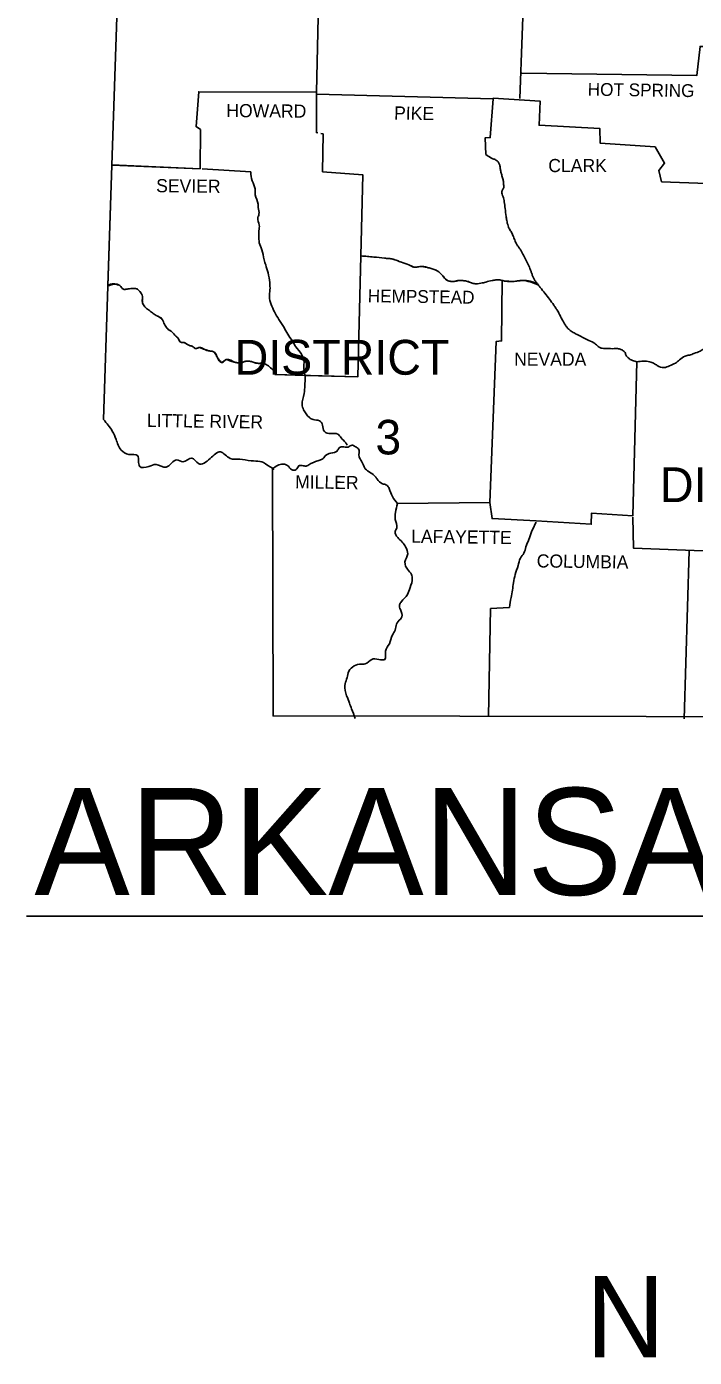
# Model space of a CAD drawing. Extents: x -17742 to 32032, y -17264 to 5867.
# Drawn here: x -17742 to -16539, y 1744 to 4141 of the extents above; entities that cross this region are included whole.
import ezdxf

# ---------------------------------------------------------------- set-up
doc = ezdxf.new("R2010")
doc.units = 0
for name, color, linetype in [('1', 7, 'Continuous'), ('2', 7, 'Continuous'), ('3', 7, 'Continuous'), ('R_Annotation', 7, 'Continuous')]:
    doc.layers.add(name, color=color, linetype=linetype)

msp = doc.modelspace()

# ---------------------------------------------------------------- linework, layer by layer
at = {"layer": '1'}
msp.add_line((-17741.9, 2539.3), (-14228.8, 2539.3), dxfattribs=at)
for points in [[(-16759.7, 4833.7), (-16761.9, 4754.5), (-16887.4, 4753.9), (-16903.9, 4739.6), (-16913.3, 4717.6), (-16927, 4718.7), (-16927.6, 4706), (-16943.5, 4704.4), (-16943, 4692.8), (-17022.8, 4695), (-17025.5, 4686.2), (-17058.6, 4685.1), (-17059.7, 4363.2), (-17087.2, 4362.6), (-17085, 4346.1), (-17111.4, 4346.7), (-17111.9, 4334.6), (-17137.8, 4334.6), (-17137.3, 4325.8), (-17175.8, 4324.7), (-17176.3, 4291.1), (-17213.8, 4294.4), (-17219.8, 4023.6)], [(-17563.4, 4638.6), (-17588.2, 3891.9)], [(-16840.6, 4354.9), (-16853.3, 4012.1)], [(-16849.4, 4057.7), (-16534.6, 4053.3), (-16528.6, 4105.6), (-16503.8, 4105.6), (-16503.3, 4149.6), (-16384.4, 4148), (-16385.5, 4121.6), (-16354.7, 4119.4), (-16354.7, 4070.9), (-16334.8, 4069.3)], [(-17219.8, 4019.8), (-17219.8, 3950.4), (-17217.5, 3950)], [(-16901.3, 4011.4), (-16901.2, 4012.6), (-16816.4, 4007.1), (-16818.6, 3963.6), (-16709.1, 3957.6), (-16708.5, 3931.2), (-16609.5, 3925.1), (-16592.4, 3895.4), (-16602.9, 3882.2), (-16597.9, 3861.8), (-16239.1, 3848.6)], [(-17212.1, 3949), (-17207.7, 3948.2), (-17208.8, 3880), (-17136.2, 3874.5), (-17139.7, 3728.4)], [(-17425.7, 3885.2), (-17338.1, 3880)], [(-17595.4, 3674.1), (-17603.4, 3433.6)], [(-16885.2, 3684.6), (-16886.3, 3575.1), (-16896.2, 3574), (-16907.2, 3283.9)], [(-16642.5, 3537.6), (-16649.6, 3260.3), (-16723.9, 3265.2), (-16724.5, 3244.9), (-16823.6, 3250.9)], [(-17299.1, 3345), (-17298, 2899.8), (-15280.9, 2896.5)], [(-16823.6, 3250.9), (-16903.4, 3255.3), (-16907.2, 3283.9), (-17074, 3282.3)], [(-16413.5, 3193.1), (-16648.5, 3201.9), (-16649.6, 3257.5)], [(-16548.4, 3197), (-16557.2, 2894.8)], [(-16872, 3095.2), (-16906.1, 3093), (-16910, 2899.2)]]:
    msp.add_lwpolyline(points, dxfattribs=at)
for points in [[(-17338.1, 3880), (-17335.4, 3863.5), (-17330.4, 3849.1), (-17329.9, 3838.1), (-17324.9, 3821.6), (-17324.9, 3815.6), (-17323.3, 3803.5), (-17325.5, 3796.9), (-17322.7, 3783.7), (-17323.3, 3773.8), (-17323.3, 3765.5), (-17322.7, 3751.7), (-17318.3, 3739.6), (-17313.9, 3721.5), (-17311.2, 3712.1), (-17306.8, 3697.8), (-17304, 3680.2), (-17303.5, 3667), (-17304.6, 3654.9), (-17301.3, 3641.1), (-17295.2, 3627.4), (-17287.5, 3614.1), (-17278.2, 3599.3), (-17271.5, 3587.7), (-17263.3, 3575.1), (-17256.7, 3564.6), (-17246.8, 3551.4), (-17242.4, 3540.4), (-17242.4, 3525), (-17240.2, 3510.7), (-17240.7, 3494.7), (-17241.8, 3480.4), (-17245.7, 3460.6), (-17242.9, 3451.2), (-17232.5, 3437.5), (-17225.9, 3433.6), (-17214.3, 3431.4), (-17208.8, 3423.7), (-17205.5, 3412.2), (-17193.9, 3408.3), (-17181.3, 3407.2), (-17175.2, 3400.6), (-17167, 3391.8), (-17164.2, 3387.4)], [(-16819.8, 3675.6), (-16816.4, 3671.4), (-16799.9, 3650.5), (-16792.2, 3639.9), (-16788.6, 3634.5), (-16785, 3629), (-16782.8, 3625.1), (-16780.8, 3621.1), (-16778.9, 3617), (-16776.8, 3613), (-16771.2, 3603.7), (-16768, 3599.3), (-16766.2, 3597.3), (-16764.1, 3595.4), (-16757.2, 3590.6), (-16749.8, 3586.6), (-16731.6, 3577.3), (-16720.1, 3571.8), (-16716.7, 3569.5), (-16713.7, 3566.7), (-16710.5, 3564), (-16708.8, 3563.1), (-16706.9, 3562.4), (-16698.4, 3561.5), (-16689.8, 3561.3), (-16683.5, 3561.3), (-16680.3, 3561.4), (-16677.2, 3561.3), (-16674.1, 3560.8), (-16671.1, 3559.8), (-16668.3, 3558.3), (-16665.6, 3556.4), (-16663.8, 3554.1), (-16662.7, 3551.4), (-16661.7, 3548.7), (-16660.1, 3546.5), (-16657.8, 3544.5), (-16655.5, 3542.8), (-16650.2, 3539.9), (-16642.5, 3537.6)], [(-16514.3, 3566.3), (-16528.6, 3556.9), (-16539.6, 3552.5), (-16547.8, 3549.8), (-16555.5, 3547.6), (-16565.4, 3541), (-16573.1, 3535.4), (-16583.6, 3530.5), (-16593.5, 3527.2), (-16605.6, 3531), (-16612.2, 3534.9), (-16619.4, 3537.6), (-16642.5, 3537.6)], [(-17603.4, 3433.6), (-17587.5, 3412.7), (-17580.8, 3397.9), (-17571.5, 3378.6), (-17557.7, 3370.9), (-17541.8, 3368.1), (-17538.5, 3349.4), (-17522, 3348.9), (-17508.7, 3352.7), (-17490.6, 3347.8), (-17471.3, 3361), (-17460.3, 3357.7), (-17444.4, 3364.3), (-17432.3, 3354.4), (-17411.3, 3363.2), (-17392.6, 3375.3), (-17375, 3363.7), (-17358, 3362.1), (-17337.6, 3359.3), (-17321.6, 3358.2), (-17307.3, 3351.1), (-17296.9, 3343.9), (-17299.1, 3345)], [(-17299.1, 3345), (-17279.8, 3353.3), (-17271.5, 3350.5), (-17264.4, 3343.4), (-17256.1, 3343.4), (-17251.7, 3350), (-17243.5, 3350.5), (-17236.9, 3350), (-17229.7, 3354.4), (-17223.7, 3357.1), (-17215.4, 3359.9), (-17209.4, 3362.1), (-17203.9, 3368.1), (-17193.9, 3373.1), (-17182.4, 3376.9), (-17179.1, 3382.4), (-17173.6, 3384.7), (-17162.6, 3384.1), (-17155.4, 3387.4), (-17149.4, 3384.7), (-17143.9, 3380.8), (-17142.8, 3366.5), (-17138.4, 3358.8), (-17131.8, 3345), (-17122.4, 3337.9), (-17113.6, 3330.7), (-17110.3, 3326.3), (-17100.9, 3318.1), (-17092.7, 3315.3), (-17088.8, 3309.3), (-17082.8, 3294.9), (-17074, 3282.3)], [(-17074, 3282.3), (-17077.3, 3266.3), (-17077.8, 3253.7), (-17075.1, 3238.8), (-17077.8, 3231.7), (-17073.4, 3221.2), (-17065.2, 3212.9), (-17059.1, 3204.1), (-17055.3, 3191.5), (-17060.2, 3177.2), (-17054.7, 3162.3), (-17049.8, 3156.8), (-17047, 3148), (-17050.9, 3130.9), (-17055.8, 3118.3), (-17066.8, 3105.6), (-17070.1, 3099.6), (-17068.5, 3091.3), (-17065.7, 3078.1), (-17068.5, 3074.3), (-17075.6, 3064.9), (-17077.8, 3054.4), (-17082.8, 3045.6), (-17088.3, 3029.7), (-17095.4, 3016.5), (-17096.5, 3001.6), (-17107.5, 3001.6), (-17120.2, 3001.6), (-17131.8, 2993.3), (-17142.2, 2992.8), (-17154.9, 2987.8), (-17162.6, 2977.4), (-17165.3, 2965.8), (-17168.6, 2954.8), (-17165.3, 2936.1), (-17160.4, 2922.9), (-17156.5, 2912.4), (-17149.9, 2895.4)], [(-16872, 3095.2), (-16869.2, 3112.8), (-16866.5, 3126.5), (-16864.8, 3139.7), (-16861.5, 3154.6), (-16856.6, 3170.6), (-16852.2, 3183.8), (-16846.1, 3193.1), (-16842.3, 3204.1), (-16837.3, 3217.3), (-16832.4, 3231.1), (-16823.6, 3248.7)]]:
    msp.add_spline(points, degree=3, dxfattribs=at)
at = {"layer": 'R_Annotation'}
for p, q in [((-17588.2, 3891.9), (-17595.4, 3674.3)), ((-16885.2, 3684.6), (-16885.2, 3684.3))]:
    msp.add_line(p, q, dxfattribs=at)
for points in [[(-17588.2, 3892.4), (-17429.5, 3885.5), (-17428.9, 3955.9), (-17436.7, 3961.4), (-17431.7, 4024.2), (-17219.8, 4023.6), (-17219.8, 4019.8), (-17219.8, 4019.8), (-16901.2, 4011.4), (-16901.3, 4011.4), (-16906.7, 3941.6), (-16915.5, 3941.1), (-16914.4, 3910.8)], [(-16914.4, 3910.8), (-16915.5, 3941.1), (-16906.7, 3941.6), (-16901.3, 4011.4), (-17219.8, 4019.8), (-17219.8, 4023.6), (-17431.7, 4024.2), (-17436.7, 3961.4), (-17428.9, 3955.9), (-17429.5, 3885.5), (-17588.2, 3891.9)], [(-17595.4, 3674.1), (-17588.2, 3891.9)], [(-17139.7, 3728.4), (-17145, 3510.7), (-17294.7, 3514.5)], [(-17294.7, 3514.5), (-17240.3, 3513.1), (-17145, 3510.7), (-17139.7, 3728.3)], [(-16885.3, 3684.3), (-16885.2, 3684.6)]]:
    msp.add_lwpolyline(points, dxfattribs=at)
for points in [[(-16914.4, 3910.8), (-16905.6, 3905.3), (-16903, 3904), (-16900.3, 3902.9), (-16897.7, 3901.8), (-16895.1, 3900.3), (-16891.6, 3896.7), (-16889.6, 3892.1), (-16888.9, 3888.9), (-16888.5, 3885.7), (-16888, 3882.6), (-16887.4, 3879.4), (-16886.5, 3876), (-16885.5, 3872.5), (-16884.5, 3869.1), (-16883.5, 3865.7), (-16882.9, 3862.1), (-16882.5, 3858.5), (-16882.4, 3854.9), (-16882.4, 3851.4), (-16883.1, 3849.4), (-16884.3, 3847.5), (-16885.4, 3845.6), (-16885.7, 3843.6), (-16884.9, 3839.3), (-16883.6, 3834.9), (-16882.3, 3830.5), (-16881.3, 3826), (-16879.7, 3813.9), (-16878, 3799.6), (-16876.4, 3789.9), (-16875.2, 3785.1), (-16873.6, 3780.4), (-16872.1, 3776.9), (-16870.2, 3773.7), (-16868.2, 3770.5), (-16866.5, 3767.1), (-16864.8, 3763.2), (-16863.3, 3759.1), (-16861.7, 3755.1), (-16859.9, 3751.2), (-16857.3, 3746.8), (-16854.4, 3742.7), (-16851.5, 3738.5), (-16848.9, 3734.1), (-16839.5, 3715.4), (-16835.1, 3705.5), (-16833.1, 3700.4), (-16831.3, 3695.2), (-16829.4, 3690), (-16828.2, 3687.5), (-16826.9, 3685.1), (-16823.5, 3680.2), (-16819.8, 3675.6)], [(-16877.2, 3794.1), (-16878, 3799.6), (-16879.7, 3813.9), (-16881.3, 3826), (-16882.3, 3830.5), (-16883.6, 3834.9), (-16884.9, 3839.3), (-16885.7, 3843.6), (-16885.4, 3845.6), (-16884.3, 3847.5), (-16883.1, 3849.4), (-16882.4, 3851.4), (-16882.4, 3854.9), (-16882.5, 3858.5), (-16882.9, 3862.1), (-16883.5, 3865.7), (-16884.5, 3869.1), (-16885.5, 3872.5), (-16886.5, 3876), (-16887.4, 3879.4), (-16888, 3882.6), (-16888.5, 3885.7), (-16888.9, 3888.9), (-16889.6, 3892.1), (-16891.6, 3896.7), (-16895.1, 3900.3), (-16897.7, 3901.8), (-16900.3, 3902.9), (-16903, 3904), (-16905.6, 3905.3), (-16914.4, 3910.8)], [(-16820.2, 3676.2), (-16823.5, 3680.2), (-16826.9, 3685.1), (-16828.2, 3687.5), (-16829.4, 3690), (-16831.3, 3695.2), (-16833.1, 3700.4), (-16835.1, 3705.5), (-16839.5, 3715.4), (-16848.9, 3734.1), (-16851.5, 3738.5), (-16854.4, 3742.7), (-16857.3, 3746.8), (-16859.9, 3751.2), (-16861.7, 3755.1), (-16863.3, 3759.1), (-16864.8, 3763.2), (-16866.5, 3767.1), (-16868.2, 3770.5), (-16870.2, 3773.7), (-16872.1, 3776.9), (-16873.6, 3780.4), (-16875.2, 3785.1), (-16876.4, 3789.9), (-16877.2, 3794.1)], [(-16819.8, 3675.8), (-16849.4, 3684), (-16865.4, 3682.4), (-16879.1, 3682.9), (-16889.6, 3685.1), (-16903.4, 3684), (-16914.4, 3681.3), (-16923.7, 3679.1), (-16935.3, 3678.5), (-16949.6, 3682.9), (-16962.2, 3684), (-16972.7, 3682.4), (-16985.4, 3685.1), (-16992, 3692.3), (-17002.4, 3701.7), (-17016.7, 3706.6), (-17029.4, 3709.4), (-17044.3, 3708.3), (-17053.1, 3712.1), (-17066.8, 3717.1), (-17082.2, 3722.6), (-17097.1, 3724.2), (-17116.3, 3726.4), (-17139.7, 3728.3)], [(-17139.7, 3728.3), (-17128, 3727.5), (-17116.3, 3726.4), (-17097.1, 3724.2), (-17089.6, 3723.6), (-17085.9, 3723.2), (-17082.2, 3722.6), (-17081.2, 3722.3), (-17080.2, 3722), (-17078.3, 3721.4), (-17074.4, 3720), (-17066.8, 3717.1), (-17053.1, 3712.1), (-17048.7, 3710.2), (-17046.5, 3709.1), (-17044.3, 3708.3), (-17042.4, 3707.9), (-17040.6, 3707.9), (-17036.9, 3708.5), (-17033.1, 3709.3), (-17029.4, 3709.4), (-17023, 3708.2), (-17019.9, 3707.4), (-17016.7, 3706.6), (-17009.4, 3704.7), (-17002.4, 3701.7), (-17000.9, 3700.7), (-16999.5, 3699.6), (-16996.9, 3697.2), (-16994.4, 3694.8), (-16992, 3692.3), (-16990.4, 3690.5), (-16988.9, 3688.7), (-16987.3, 3686.8), (-16985.4, 3685.1), (-16983.8, 3684.2), (-16982.3, 3683.5), (-16979.1, 3682.6), (-16972.7, 3682.4), (-16970.1, 3682.7), (-16967.5, 3683.3), (-16964.9, 3683.8), (-16962.2, 3684), (-16955.9, 3683.8), (-16949.6, 3682.9), (-16946, 3682), (-16942.4, 3680.6), (-16938.9, 3679.3), (-16935.3, 3678.5), (-16932.4, 3678.3), (-16929.5, 3678.3), (-16923.7, 3679.1), (-16914.4, 3681.3), (-16903.4, 3684), (-16896.5, 3685.1), (-16893, 3685.2), (-16889.6, 3685.1), (-16885.3, 3684.3)], [(-17294.7, 3514.5), (-17294.7, 3517.8), (-17300.2, 3525), (-17308.4, 3531.6), (-17317.2, 3534.9), (-17325.5, 3534.9), (-17338.7, 3538.2), (-17345.8, 3538.7), (-17355.2, 3536), (-17365.7, 3536.5), (-17382.2, 3541.5), (-17391, 3536.5), (-17398.1, 3545.4), (-17405.3, 3555.8), (-17411.3, 3556.9), (-17422.3, 3560.2), (-17430.6, 3563.5), (-17437.2, 3561.3), (-17443.8, 3565.7), (-17449.9, 3567.4), (-17458.1, 3572.3), (-17464.2, 3572.9), (-17469.7, 3580.6), (-17473, 3583.9), (-17480.1, 3591.6), (-17486.7, 3596), (-17492.2, 3603.1), (-17496.6, 3611.9), (-17497.7, 3614.1), (-17508.7, 3621.3), (-17515.4, 3625.7), (-17522.5, 3631.2), (-17529.1, 3636.7), (-17533, 3643.9), (-17533.5, 3647.2), (-17533, 3655.4), (-17537.9, 3664.2), (-17544, 3669.2), (-17552.2, 3669.7), (-17561, 3668.6), (-17566, 3668.1), (-17574.2, 3675.2), (-17595.4, 3674.3)], [(-17595.4, 3674.3), (-17594.5, 3675.3), (-17593.4, 3676.2), (-17590.9, 3677.3), (-17585.1, 3677.9), (-17579.2, 3677), (-17576.6, 3676.1), (-17574.2, 3675.2), (-17573.2, 3674.6), (-17572.2, 3673.5), (-17570.4, 3671.1), (-17568.4, 3668.9), (-17566, 3668.1), (-17561, 3668.6), (-17552.2, 3669.7), (-17548.1, 3669.9), (-17544, 3669.2), (-17542.2, 3668.4), (-17540.7, 3667.2), (-17537.9, 3664.2), (-17536.2, 3662.1), (-17534.8, 3660), (-17533, 3655.4), (-17532.9, 3653.4), (-17533.1, 3651.3), (-17533.5, 3649.2), (-17533.5, 3647.2), (-17533, 3643.9), (-17532.3, 3641.9), (-17531.5, 3640), (-17529.1, 3636.7), (-17522.5, 3631.2), (-17515.4, 3625.7), (-17512.1, 3623.5), (-17508.7, 3621.3), (-17507.3, 3620.5), (-17505.8, 3619.7), (-17502.6, 3618.3), (-17499.8, 3616.6), (-17497.7, 3614.1), (-17496.6, 3611.9), (-17492.2, 3603.1), (-17489.8, 3599.4), (-17488.3, 3597.6), (-17486.7, 3596), (-17485.2, 3594.8), (-17483.4, 3593.8), (-17481.7, 3592.8), (-17480.1, 3591.6), (-17473, 3583.9), (-17469.7, 3580.6), (-17468.2, 3578.7), (-17467, 3576.7), (-17465.8, 3574.6), (-17464.2, 3572.9), (-17462.9, 3572.3), (-17461.3, 3572.4), (-17459.7, 3572.6), (-17458.3, 3572.4)], [(-16885.2, 3684.3), (-16882.2, 3683.5), (-16879.1, 3682.9), (-16875.7, 3682.7), (-16872.3, 3682.5), (-16865.4, 3682.4), (-16861.4, 3682.6), (-16857.4, 3683.2), (-16853.4, 3683.7), (-16849.4, 3684), (-16841.9, 3683.8), (-16834.5, 3682.6), (-16827.2, 3680.2), (-16820.2, 3676.2)], [(-17458.3, 3572.4), (-17458.1, 3572.3), (-17456, 3571.2), (-17454, 3569.8), (-17452, 3568.5), (-17449.9, 3567.4), (-17448.4, 3566.9), (-17446.8, 3566.5), (-17445.3, 3566.2), (-17443.8, 3565.7), (-17442.1, 3564.8), (-17440.5, 3563.5), (-17438.9, 3562.2), (-17437.2, 3561.3), (-17435.6, 3561.5), (-17433.9, 3562.4), (-17432.2, 3563.4), (-17430.6, 3563.5), (-17428.5, 3562.7), (-17426.5, 3561.9), (-17424.4, 3561), (-17422.3, 3560.2), (-17416.9, 3558.5), (-17411.3, 3556.9), (-17409.8, 3556.7), (-17408.2, 3556.6), (-17406.7, 3556.4), (-17405.3, 3555.8), (-17404.6, 3555.3), (-17404, 3554.7), (-17403, 3553.5), (-17401.3, 3550.9), (-17399.8, 3548.1), (-17398.1, 3545.4), (-17394.7, 3540.8), (-17392.9, 3538.6), (-17391, 3536.5), (-17390, 3536.1), (-17389, 3536.4), (-17386.8, 3538.3), (-17384.5, 3540.6), (-17382.2, 3541.5), (-17378.1, 3540.4), (-17374, 3538.9), (-17369.9, 3537.5), (-17365.7, 3536.5), (-17355.2, 3536), (-17352.8, 3536.5), (-17350.5, 3537.4), (-17348.2, 3538.3), (-17345.8, 3538.7), (-17338.7, 3538.2), (-17335.4, 3537.5), (-17332.1, 3536.5), (-17328.8, 3535.6), (-17325.5, 3534.9), (-17323.4, 3534.8), (-17321.4, 3534.9), (-17319.3, 3535), (-17317.2, 3534.9), (-17308.4, 3531.6), (-17300.2, 3525), (-17294.7, 3517.8), (-17294.7, 3514.5)]]:
    msp.add_spline(points, degree=3, dxfattribs=at)

# ---------------------------------------------------------------- texts
at = {"layer": '2'}
for s, height, rotation, p in [('HOT SPRING', 23.11, 359.2216, (-16731.1, 4017)), ('HOWARD', 23.67, 359.5145, (-17382.2, 3978.5)), ('PIKE', 23.66, 359.0452, (-17080, 3974.1)), ('SEVIER', 23.67, 359.4271, (-17508.7, 3843.1)), ('HEMPSTEAD', 23.11, 359.1885, (-17127.4, 3645)), ('LITTLE RIVER', 23.666, 359.1697, (-17525.3, 3420.4)), ('MILLER', 23.66, 359.1319, (-17258.3, 3309.8)), ('LAFAYETTE', 23.66, 359.1839, (-17049.2, 3211.8)), ('COLUMBIA', 23.66, 359.2125, (-16823, 3167.3))]:
    msp.add_text(s, height=height, rotation=rotation, dxfattribs=at).set_placement(p)
for s, height, p in [('CLARK', 23.67, (-16802, 3879.3)), ('NEVADA', 23.67, (-16863.7, 3530.5)), ('ARKANSAS HIGHWAY DISTRICT 3', 192.623, (-17727.9, 2577.3))]:
    msp.add_text(s, height=height, dxfattribs=at).set_placement(p)
at = {"layer": '3'}
for s, height, p in [('DISTRICT', 62.74, (-17367.1, 3514.4)), ('3', 62.2, (-17113.4, 3370.8)), ('DISTRICT 7', 62.74, (-16600.8, 3284.8))]:
    msp.add_text(s, height=height, dxfattribs=at).set_placement(p)
at = {"layer": 'R_Annotation'}
msp.add_text('N', height=146.7, dxfattribs=at).set_placement((-16733.7, 1744.3))

doc.saveas('drawing.dxf')
